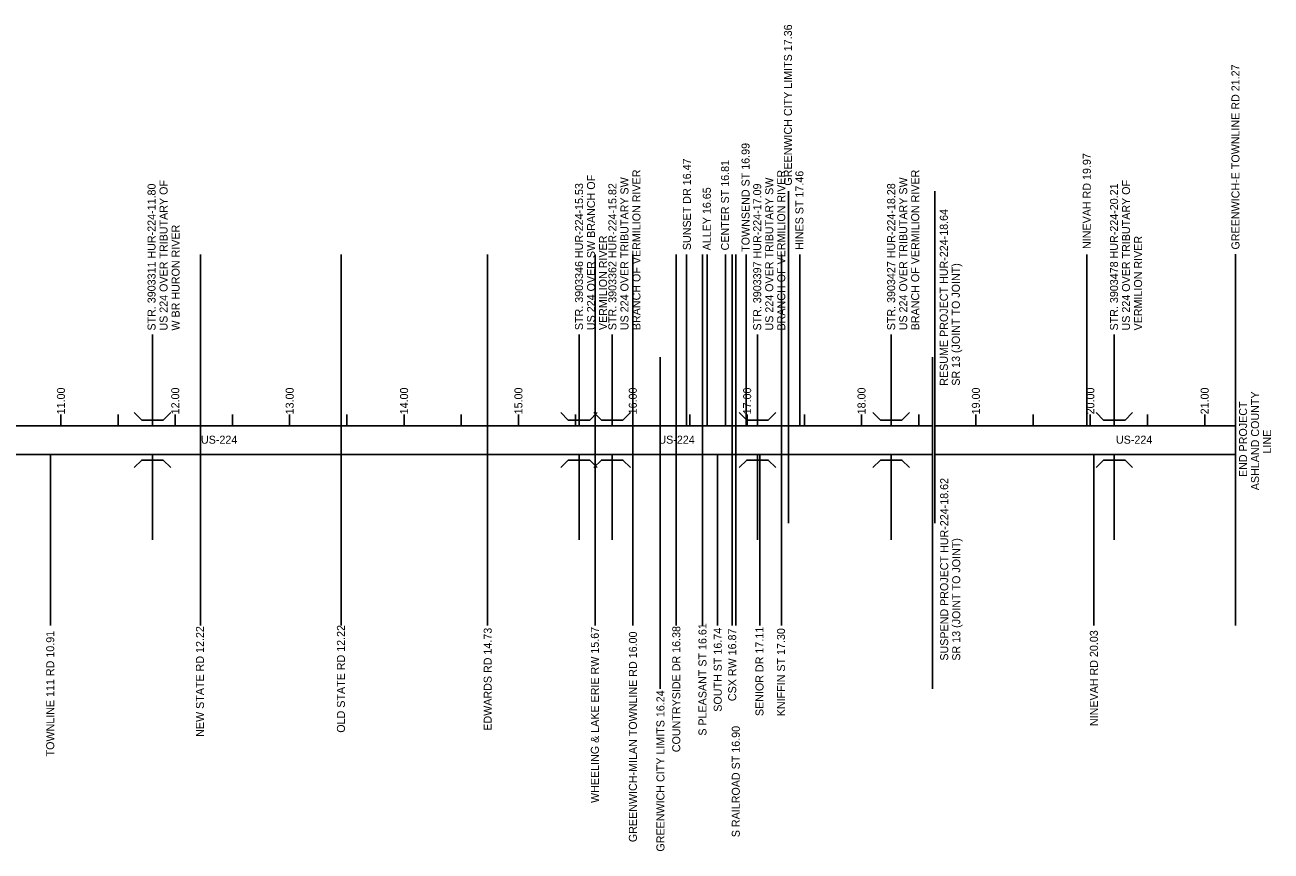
# Model space of a CAD drawing. Extents: x 20550.2 to 20593.9, y 6180.6 to 6241.4.
# Drawn here: x 20572.06 to 20593.87, y 6226.93 to 6241.39 of the extents above; entities that cross this region are included whole.
import ezdxf

# ---------------------------------------------------------------- set-up
doc = ezdxf.new("R2010")
doc.units = 0
for name, color, linetype in [('CM_Corridor_Range_Design', 7, 'Continuous'), ('DR_X_Culvert', 7, 'Continuous'), ('MD_X_Asphalt_Pavement', 7, 'Continuous'), ('PV_X_EOP', 7, 'Continuous'), ('RD_X_RR_1', 7, 'Continuous'), ('SH_Data', 7, 'Continuous'), ('SH_Text', 7, 'Continuous')]:
    doc.layers.add(name, color=color, linetype=linetype)

msp = doc.modelspace()

# ---------------------------------------------------------------- linework, layer by layer
at = {"layer": 'CM_Corridor_Range_Design'}
for p, q in [((20585.42, 6232.672), (20585.42, 6238.478)), ((20587.983, 6232.672), (20587.983, 6238.478)), ((20593.248, 6237.377), (20593.248, 6230.878)), ((20583.177, 6235.575), (20583.177, 6229.769)), ((20587.943, 6235.575), (20587.943, 6229.769))]:
    msp.add_line(p, q, dxfattribs=at)
at = {"layer": 'DR_X_Culvert'}
for p, q in [((20574.288, 6235.972), (20574.288, 6234.474)), ((20581.756, 6235.972), (20581.756, 6234.474)), ((20582.337, 6235.972), (20582.337, 6234.474)), ((20584.879, 6235.972), (20584.879, 6234.474)), ((20587.222, 6235.972), (20587.222, 6234.474)), ((20591.126, 6235.972), (20591.126, 6234.474)), ((20574.288, 6234.374), (20574.288, 6234.474)), ((20581.756, 6234.374), (20581.756, 6234.474)), ((20582.337, 6234.374), (20582.337, 6234.474)), ((20584.879, 6234.374), (20584.879, 6234.474)), ((20587.222, 6234.374), (20587.222, 6234.474)), ((20591.126, 6234.374), (20591.126, 6234.474)), ((20574.288, 6233.873), (20574.288, 6233.773)), ((20574.288, 6233.873), (20574.288, 6232.376)), ((20581.756, 6233.873), (20581.756, 6233.773)), ((20581.756, 6233.873), (20581.756, 6232.376)), ((20582.337, 6233.873), (20582.337, 6233.773)), ((20582.337, 6233.873), (20582.337, 6232.376)), ((20584.879, 6233.873), (20584.879, 6233.773)), ((20584.879, 6233.873), (20584.879, 6232.376)), ((20587.222, 6233.873), (20587.222, 6233.773)), ((20587.222, 6233.873), (20587.222, 6232.376)), ((20591.126, 6233.873), (20591.126, 6233.773)), ((20591.126, 6233.873), (20591.126, 6232.376))]:
    msp.add_line(p, q, dxfattribs=at)
for points in [[(20573.967, 6234.607), (20574.1, 6234.474), (20574.476, 6234.474), (20574.608, 6234.607)], [(20581.435, 6234.607), (20581.568, 6234.474), (20581.944, 6234.474), (20582.076, 6234.607)], [(20582.016, 6234.607), (20582.149, 6234.474), (20582.524, 6234.474), (20582.657, 6234.607)], [(20584.559, 6234.607), (20584.692, 6234.474), (20585.067, 6234.474), (20585.2, 6234.607)], [(20586.901, 6234.607), (20587.034, 6234.474), (20587.409, 6234.474), (20587.542, 6234.607)], [(20590.806, 6234.607), (20590.938, 6234.474), (20591.314, 6234.474), (20591.446, 6234.607)], [(20573.967, 6233.641), (20574.1, 6233.773), (20574.476, 6233.773), (20574.608, 6233.641)], [(20581.435, 6233.641), (20581.568, 6233.773), (20581.944, 6233.773), (20582.076, 6233.641)], [(20582.016, 6233.641), (20582.149, 6233.773), (20582.524, 6233.773), (20582.657, 6233.641)], [(20584.559, 6233.641), (20584.692, 6233.773), (20585.067, 6233.773), (20585.2, 6233.641)], [(20586.901, 6233.641), (20587.034, 6233.773), (20587.409, 6233.773), (20587.542, 6233.641)], [(20590.806, 6233.641), (20590.938, 6233.773), (20591.314, 6233.773), (20591.446, 6233.641)]]:
    msp.add_lwpolyline(points, dxfattribs=at)
at = {"layer": 'MD_X_Asphalt_Pavement'}
for p, q in [((20575.129, 6237.369), (20575.129, 6230.878)), ((20577.591, 6237.369), (20577.591, 6230.878)), ((20580.154, 6237.369), (20580.154, 6230.878)), ((20582.697, 6237.369), (20582.697, 6230.878)), ((20583.458, 6237.369), (20583.458, 6230.878)), ((20583.638, 6237.369), (20583.638, 6234.374)), ((20583.918, 6237.369), (20583.918, 6230.878)), ((20583.998, 6237.369), (20583.998, 6234.374)), ((20584.319, 6237.369), (20584.319, 6234.374)), ((20584.499, 6237.369), (20584.499, 6230.878)), ((20584.679, 6237.369), (20584.679, 6234.374)), ((20585.3, 6237.369), (20585.3, 6230.878)), ((20585.62, 6237.369), (20585.62, 6234.374)), ((20590.645, 6237.369), (20590.645, 6234.374)), ((20593.248, 6237.369), (20593.248, 6230.878)), ((20572.506, 6233.873), (20572.506, 6230.878)), ((20584.178, 6233.873), (20584.178, 6230.878)), ((20584.919, 6233.873), (20584.919, 6230.878)), ((20590.766, 6233.873), (20590.766, 6230.878))]:
    msp.add_line(p, q, dxfattribs=at)
at = {"layer": 'PV_X_EOP'}
for p, q in [((20563.636, 6234.374), (20587.943, 6234.374)), ((20587.983, 6234.374), (20593.248, 6234.374)), ((20563.636, 6233.873), (20587.943, 6233.873)), ((20587.983, 6233.873), (20593.248, 6233.873))]:
    msp.add_line(p, q, dxfattribs=at)
at = {"layer": 'RD_X_RR_1'}
for p, q in [((20582.036, 6237.369), (20582.036, 6230.878)), ((20584.439, 6237.369), (20584.439, 6230.878))]:
    msp.add_line(p, q, dxfattribs=at)
at = {"layer": 'SH_Data'}
for p, q in [((20572.686, 6234.374), (20572.686, 6234.574)), ((20573.687, 6234.374), (20573.687, 6234.574)), ((20574.688, 6234.374), (20574.688, 6234.574)), ((20575.689, 6234.374), (20575.689, 6234.574)), ((20576.69, 6234.374), (20576.69, 6234.574)), ((20577.692, 6234.374), (20577.692, 6234.574)), ((20578.693, 6234.374), (20578.693, 6234.574)), ((20579.694, 6234.374), (20579.694, 6234.574)), ((20580.695, 6234.374), (20580.695, 6234.574)), ((20581.696, 6234.374), (20581.696, 6234.574)), ((20582.697, 6234.374), (20582.697, 6234.574)), ((20583.698, 6234.374), (20583.698, 6234.574)), ((20584.699, 6234.374), (20584.699, 6234.574)), ((20585.7, 6234.374), (20585.7, 6234.574)), ((20586.701, 6234.374), (20586.701, 6234.574)), ((20587.702, 6234.374), (20587.702, 6234.574)), ((20588.703, 6234.374), (20588.703, 6234.574)), ((20589.704, 6234.374), (20589.704, 6234.574)), ((20590.705, 6234.374), (20590.705, 6234.574)), ((20591.707, 6234.374), (20591.707, 6234.574)), ((20592.708, 6234.374), (20592.708, 6234.574))]:
    msp.add_line(p, q, dxfattribs=at)

# ---------------------------------------------------------------- texts
at = {"layer": 'SH_Text'}
for s, height, p in [('GREENWICH CITY LIMITS 17.36', 0.14015, (20585.483, 6238.576)), ('GREENWICH-E TOWNLINE RD 21.27', 0.14015, (20593.317, 6237.459)), ('TOWNSEND ST 16.99', 0.14015, (20584.741, 6237.418)), ('NINEVAH RD 19.97', 0.14015, (20590.715, 6237.468)), ('SUNSET DR 16.47', 0.14015, (20583.714, 6237.448)), ('CENTER ST 16.81', 0.14015, (20584.382, 6237.443)), ('US 224 OVER SW BRANCH OF', 0.14015, (20582.036, 6236.048)), ('US 224 OVER TRIBUTARY SW ', 0.14015, (20582.621, 6236.047)), ('BRANCH OF VERMILION RIVER', 0.14015, (20582.831, 6236.047)), ('US 224 OVER TRIBUTARY SW ', 0.14015, (20585.156, 6236.041)), ('BRANCH OF VERMILION RIVER', 0.14015, (20585.366, 6236.041)), ('HINES ST 17.46', 0.14015, (20585.684, 6237.452)), ('US 224 OVER TRIBUTARY SW ', 0.14015, (20587.501, 6236.045)), ('BRANCH OF VERMILION RIVER', 0.14015, (20587.711, 6236.045)), ('STR. 3903311 HUR-224-11.80', 0.14015, (20574.343, 6236.04)), ('US 224 OVER TRIBUTARY OF ', 0.14015, (20574.553, 6236.04)), ('STR. 3903346 HUR-224-15.53', 0.14015, (20581.826, 6236.048)), ('STR. 3903362 HUR-224-15.82 ', 0.14015, (20582.41, 6236.047)), ('ALLEY 16.65', 0.14015, (20584.063, 6237.443)), ('STR. 3903397 HUR-224-17.09 ', 0.14015, (20584.945, 6236.041)), ('STR. 3903427 HUR-224-18.28 ', 0.14015, (20587.29, 6236.045)), ('STR. 3903478 HUR-224-20.21 ', 0.14015, (20591.191, 6236.042)), ('US 224 OVER TRIBUTARY OF ', 0.14015, (20591.401, 6236.042)), ('RESUME PROJECT HUR-224-18.64', 0.14015, (20588.212, 6235.075)), ('W BR HURON RIVER', 0.14015, (20574.764, 6236.04)), ('VERMILION RIVER', 0.14015, (20582.246, 6236.048)), ('VERMILION RIVER', 0.14015, (20591.612, 6236.042)), ('SR 13 (JOINT TO JOINT)', 0.14015, (20588.422, 6235.075)), ('11.00', 0.1402, (20572.756, 6234.574)), ('12.00', 0.1402, (20574.758, 6234.574)), ('13.00', 0.1402, (20576.761, 6234.574)), ('14.00', 0.1402, (20578.763, 6234.574)), ('15.00', 0.1402, (20580.765, 6234.574)), ('16.00', 0.1402, (20582.767, 6234.574)), ('17.00', 0.1402, (20584.769, 6234.574)), ('18.00', 0.1402, (20586.771, 6234.574)), ('19.00', 0.1402, (20588.773, 6234.574)), ('20.00', 0.1402, (20590.776, 6234.574)), ('21.00', 0.1402, (20592.778, 6234.574)), ('END PROJECT', 0.14015, (20593.45, 6233.477)), ('ASHLAND COUNTY ', 0.14015, (20593.66, 6233.246)), ('LINE', 0.1402, (20593.87, 6233.889)), ('SUSPEND PROJECT HUR-224-18.62', 0.14015, (20588.218, 6230.263)), ('SR 13 (JOINT TO JOINT)', 0.14015, (20588.429, 6230.263)), ('NEW STATE RD 12.22', 0.14015, (20575.19, 6228.93)), ('OLD STATE RD 12.22', 0.14015, (20577.658, 6229.002)), ('WHEELING & LAKE ERIE RW 15.67', 0.14015, (20582.103, 6227.772)), ('COUNTRYSIDE DR 16.38', 0.14015, (20583.528, 6228.661)), ('S PLEASANT ST 16.61', 0.14015, (20583.987, 6228.95)), ('SENIOR DR 17.11', 0.14015, (20584.985, 6229.293)), ('TOWNLINE 111 RD 10.91', 0.14015, (20572.569, 6228.587)), ('EDWARDS RD 14.73', 0.14015, (20580.227, 6229.037)), ('GREENWICH-MILAN TOWNLINE RD 16.00', 0.14015, (20582.769, 6227.087)), ('SOUTH ST 16.74', 0.14015, (20584.254, 6229.369)), ('CSX RW 16.87', 0.14015, (20584.507, 6229.554)), ('KNIFFIN ST 17.30', 0.14015, (20585.361, 6229.29)), ('NINEVAH RD 20.03', 0.14015, (20590.838, 6229.118)), ('GREENWICH CITY LIMITS 16.24', 0.14015, (20583.251, 6226.921)), ('S RAILROAD ST 16.90', 0.14015, (20584.57, 6227.173))]:
    msp.add_text(s, height=height, rotation=90, dxfattribs=at).set_placement(p)
for p in [(20575.138, 6234.06), (20583.146, 6234.06), (20591.155, 6234.06)]:
    msp.add_text('US-224', height=0.1402, dxfattribs=at).set_placement(p)

doc.saveas('drawing.dxf')
